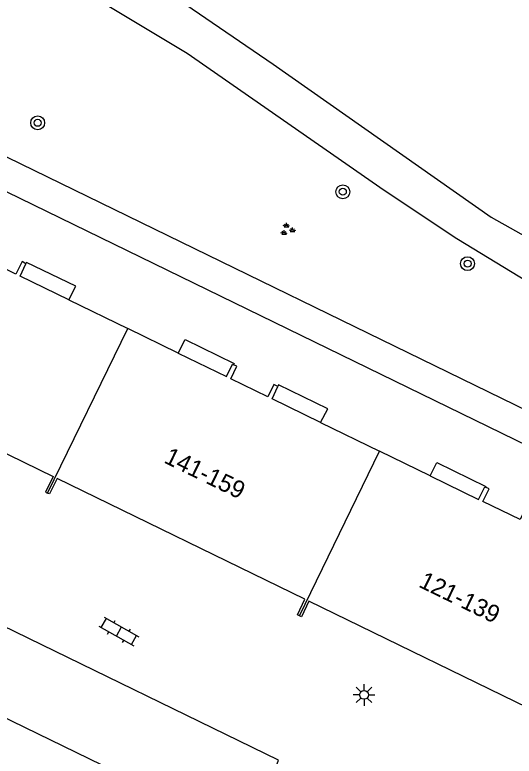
# Model space of a CAD drawing. Extents: x 130998 to 133001, y 398999 to 403002.
# Drawn here: x 131039.14 to 131067.85, y 399083.14 to 399125.77 of the extents above; entities that cross this region are included whole.
import ezdxf

# ---------------------------------------------------------------- set-up
doc = ezdxf.new("R2010")
doc.units = 0
for name, color, linetype in [('gg-anno-huisnummerreeks BGT', 7, 'Continuous'), ('gg-bbg-hoofdgebouw', 7, 'Continuous'), ('gg-bbg-onder overbouw', 7, 'Continuous'), ('gg-bbg-pand overbouw', 7, 'Continuous'), ('gg-bbg-tussenscheiding', 7, 'Continuous'), ('gg-knt-verharding', 7, 'Continuous'), ('gg-knt-verharding nz', 7, 'Continuous'), ('gt-grn-groengrens', 7, 'Continuous'), ('gt-symb-boom', 7, 'Continuous'), ('gt-symb-groenvak', 7, 'Continuous'), ('gt-symb-klinker verharding', 7, 'Continuous'), ('gt-symb-lichtmast', 7, 'Continuous')]:
    doc.layers.add(name, color=color, linetype=linetype)

# ---------------------------------------------------------------- blocks, each defined once
blk = doc.blocks.new('gt0-LMAST')
at = {"layer": 'gt-symb-lichtmast'}
for p, q in [((-0.182, 0.173), (-0.447, 0.438)), ((-0.005, 0.246), (-0.005, 0.621)), ((0.172, 0.173), (0.437, 0.438)), ((-0.255, -0.004), (-0.63, -0.004)), ((-0.182, -0.181), (-0.447, -0.446)), ((-0.005, -0.254), (-0.005, -0.629)), ((0.437, -0.446), (0.172, -0.181)), ((0.245, -0.004), (0.62, -0.004))]:
    blk.add_line(p, q, dxfattribs=at)
blk.add_circle((-0.005, -0.004), 0.25, dxfattribs=at)
blk = doc.blocks.new('gt0-BOOM')
at = {"layer": 'gt-symb-boom'}
for radius in [0.4, 0.2]:
    blk.add_circle((0, 0), radius, dxfattribs=at)
blk = doc.blocks.new('gt0-GRVAK')
at = {"layer": 'gt-symb-groenvak'}
for p, q in [((-0.11, 0.189), (-0.228, 0.24)), ((-0.182, 0.153), (0.088, 0.153)), ((-0.091, 0.211), (-0.156, 0.322)), ((-0.047, 0.214), (-0.047, 0.393)), ((-0.004, 0.211), (0.061, 0.322)), ((0.015, 0.189), (0.133, 0.24)), ((0.262, -0.052), (0.197, 0.059)), ((0.305, -0.049), (0.305, 0.13)), ((0.349, -0.052), (0.414, 0.059)), ((-0.245, -0.228), (-0.363, -0.177)), ((-0.318, -0.264), (-0.047, -0.264)), ((-0.226, -0.206), (-0.291, -0.095)), ((-0.183, -0.203), (-0.183, -0.024)), ((-0.139, -0.206), (-0.074, -0.095)), ((-0.12, -0.228), (-0.002, -0.177)), ((0.243, -0.074), (0.125, -0.023)), ((0.17, -0.11), (0.441, -0.11)), ((0.368, -0.074), (0.486, -0.023))]:
    blk.add_line(p, q, dxfattribs=at)
blk = doc.blocks.new('gt0-KL1')
at = {"layer": 'gt-symb-klinker verharding'}
for p, q in [((-0.5, 0.3), (-0.5, 0.45)), ((0.5, 0.3), (0.5, 0.45)), ((-1.15, 0.3), (1.15, 0.3)), ((-1, -0.3), (-1, 0.3)), ((0, -0.3), (0, 0.3)), ((1, -0.3), (1, 0.3)), ((-1.15, -0.3), (1.15, -0.3)), ((-0.5, -0.45), (-0.5, -0.3)), ((0.5, -0.45), (0.5, -0.3))]:
    blk.add_line(p, q, dxfattribs=at)

msp = doc.modelspace()

# ---------------------------------------------------------------- linework, layer by layer
at = {"layer": 'gg-bbg-hoofdgebouw'}
for p, q in [((131042.253, 399109.382), (131045.632, 399107.735)), ((131048.525, 399106.326), (131045.632, 399107.735)), ((131056.715, 399102.335), (131060.113, 399100.679)), ((131063.018, 399099.264), (131060.113, 399100.679))]:
    msp.add_line(p, q, dxfattribs=at)
for points in [[(131039.776, 399111.464), (131039.553, 399111.581), (131039.205, 399110.867), (131037.059, 399111.912), (131037.403, 399112.617), (131037.23, 399112.708)], [(131025.991, 399105.49), (131026.261, 399105.36), (131026.741, 399106.35), (131041.338, 399099.232), (131040.901, 399098.332), (131041.018, 399098.276)], [(131054.256, 399104.406), (131054.028, 399104.514), (131053.686, 399103.811), (131051.554, 399104.85), (131051.901, 399105.562), (131051.72, 399105.65)], [(131055.498, 399091.214), (131055.381, 399091.271), (131055.818, 399092.17), (131041.572, 399099.118), (131041.135, 399098.219), (131041.018, 399098.276)], [(131068.724, 399097.344), (131068.525, 399097.444), (131068.186, 399096.746), (131066.054, 399097.785), (131066.408, 399098.51), (131066.194, 399098.614)], [(131069.921, 399084.07), (131069.651, 399084.2), (131070.131, 399085.19), (131056.051, 399092.056), (131055.615, 399091.157), (131055.498, 399091.214)]]:
    msp.add_lwpolyline(points, dxfattribs=at)
at = {"layer": 'gg-bbg-onder overbouw'}
for points in [[(131042.253, 399109.382), (131039.451, 399110.747), (131039.776, 399111.464)], [(131048.525, 399106.326), (131051.302, 399104.973), (131051.649, 399105.685), (131051.72, 399105.65)], [(131056.715, 399102.335), (131053.933, 399103.691), (131054.256, 399104.406)], [(131063.018, 399099.264), (131065.802, 399097.907), (131066.156, 399098.633), (131066.194, 399098.614)]]:
    msp.add_lwpolyline(points, dxfattribs=at)
at = {"layer": 'gg-bbg-pand overbouw'}
for points in [[(131042.253, 399109.382), (131042.655, 399110.17), (131039.813, 399111.535), (131039.776, 399111.464)], [(131048.525, 399106.326), (131048.938, 399107.098), (131051.751, 399105.714), (131051.72, 399105.65)], [(131056.715, 399102.335), (131057.13, 399103.113), (131054.297, 399104.493), (131054.256, 399104.406)], [(131063.018, 399099.264), (131063.401, 399100.027), (131066.215, 399098.658), (131066.194, 399098.614)]]:
    msp.add_lwpolyline(points, dxfattribs=at)
at = {"layer": 'gg-bbg-tussenscheiding'}
for p, q in [((131041.018, 399098.276), (131045.632, 399107.735)), ((131055.498, 399091.214), (131060.113, 399100.679))]:
    msp.add_line(p, q, dxfattribs=at)
at = {"layer": 'gg-knt-verharding'}
for points in [[(131044.684, 399128.836), (131046.695, 399127.864), (131048.181, 399126.927), (131053.99, 399122.936), (131066.515, 399114.144), (131071.331, 399111.435), (131074.555, 399110.125)], [(131043.11, 399127.145), (131049.051, 399123.565), (131060.364, 399115.683), (131064.543, 399112.903), (131068.605, 399110.431)], [(131022.511, 399098.397), (131020.472, 399094.157), (131052.245, 399078.688), (131054.218, 399082.707)]]:
    msp.add_lwpolyline(points, dxfattribs=at)
at = {"layer": 'gg-knt-verharding nz'}
msp.add_lwpolyline([(131054.218, 399082.707), (131054.304, 399082.906), (131022.511, 399098.397)], dxfattribs=at)
at = {"layer": 'gt-grn-groengrens'}
msp.add_lwpolyline([(131077.124, 399098.838), (131033.305, 399120.202), (131032.495, 399118.602), (131076.329, 399097.227)], dxfattribs=at)

# ---------------------------------------------------------------- block references
at = {"layer": 'gt-symb-boom'}
for p in [(131040.453, 399119.565), (131057.995, 399115.6), (131065.168, 399111.465)]:
    msp.add_blockref('gt0-BOOM', p, dxfattribs=at)
at = {"layer": 'gt-symb-groenvak'}
msp.add_blockref('gt0-GRVAK', (131054.803, 399113.42), dxfattribs=at)
at = {"layer": 'gt-symb-klinker verharding', "rotation": -29.6169097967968}
msp.add_blockref('gt0-KL1', (131045.126, 399090.31), dxfattribs=at)
at = {"layer": 'gt-symb-lichtmast'}
msp.add_blockref('gt0-LMAST', (131059.219, 399086.666), dxfattribs=at)

# ---------------------------------------------------------------- texts
at = {"layer": 'gg-anno-huisnummerreeks BGT'}
for s, p in [('141-159', (131047.652, 399100.047)), ('121-139', (131062.3, 399092.903))]:
    msp.add_text(s, height=1, rotation=334, dxfattribs=at).set_placement(p)

doc.saveas('drawing.dxf')
